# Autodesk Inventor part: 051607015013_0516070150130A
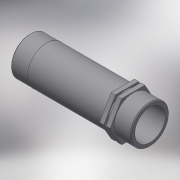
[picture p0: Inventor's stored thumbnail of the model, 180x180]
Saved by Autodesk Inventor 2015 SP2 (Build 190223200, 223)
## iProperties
Created: 2017-05
Part Number: 051607015013_0516070150130A
Material: Generic
Description: PLASSON RISER 1.1/2"-1.1/4"
Document SubType Name: Modeling
Designer: KIM
Mass: 20.3153 g
Surface Area: 184.457 cm^2
Volume: 20.3153 cm^3
Density: 1 g/cm^3
Appearance: Default
Author: KIM
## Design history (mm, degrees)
derived "051607.ipt"
feature "Solid1::051607.ipt"
tag "TaggingFeature1"
body "Solid1"
other parameters: "d1" = 47.803, "d3" = 33.528, "d5" = 21, "d6" = 5.25, "d8" = 1.05, "d12" = 0, "d13" = 2.625, "d15" = 21, "d17" = 0, "d18" = 41.91, "R_" = 47.803, "l_2" = 21, "R_1" = 41.91
